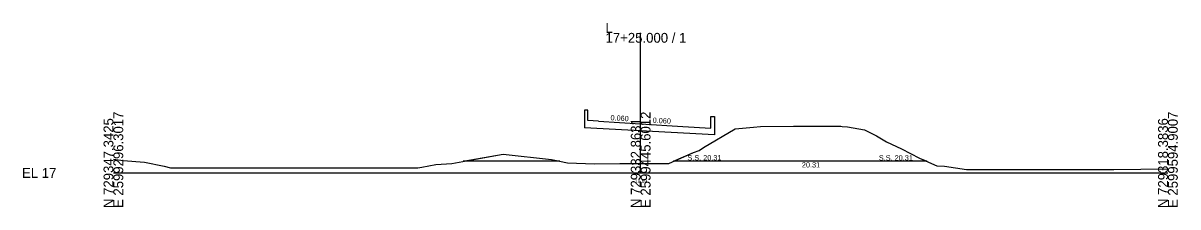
# Model space of a CAD drawing. Extents: x -26 to 3303, y -10 to 9555.
# Drawn here: x 974.3 to 1302.8, y 4490.3 to 4542.7 of the extents above; entities that cross this region are included whole.
import ezdxf

# ---------------------------------------------------------------- set-up
doc = ezdxf.new("R2010")
doc.units = 0
for name, color, linetype in [('Exist Cross Section Cell', 7, 'Continuous'), ('Exist XS Center Line Elevation Label', 7, 'Continuous'), ('Exist XS Ground Line', 7, 'Continuous'), ('Prop XS Bridge', 7, 'Continuous'), ('Prop XS Ditch Standard Text', 7, 'Continuous'), ('Prop XS Dump Level', 7, 'Continuous'), ('Prop XS Earthwork Shape', 7, 'Continuous'), ('Prop XS Finish Grade Earthwork', 7, 'Continuous'), ('Prop XS SE Text', 7, 'Continuous'), ('Prop XS SS Elevation Text', 7, 'Continuous')]:
    doc.layers.add(name, color=color, linetype=linetype)

msp = doc.modelspace()

# ---------------------------------------------------------------- linework, layer by layer
at = {"layer": 'Exist Cross Section Cell'}
for p, q in [((1150, 4500), (1150, 4539.91)), ((1000, 4500), (1150, 4500)), ((1150, 4500), (1300, 4500))]:
    msp.add_line(p, q, dxfattribs=at)
at = {"layer": 'Exist XS Ground Line'}
msp.add_lwpolyline([(1000, 4503.89), (1002.73, 4503.59), (1008.85, 4503.1), (1014.43, 4501.9), (1016.24, 4501.47), (1040.03, 4501.47), (1049.38, 4501.47), (1064.82, 4501.47), (1086.62, 4501.47), (1087.71, 4501.66), (1091.71, 4502.36), (1096.3, 4502.73), (1110.93, 4505.38), (1124.67, 4503.79), (1129.16, 4502.85), (1136.85, 4502.62), (1144.09, 4502.65), (1146.63, 4502.67), (1150, 4502.69), (1158.05, 4502.73), (1165.07, 4505.79), (1166.64, 4506.37), (1167.83, 4507.27), (1176.87, 4512.53), (1182.11, 4513), (1184.13, 4513.24), (1193.5, 4513.29), (1195.77, 4513.29), (1206.42, 4513.3), (1206.94, 4513.3), (1207.3, 4513.27), (1208.82, 4513.11), (1213.67, 4512.28), (1217.05, 4510.58), (1219.93, 4508.83), (1224.23, 4506.87), (1229.28, 4504.25), (1234.25, 4502.07), (1236.47, 4501.9), (1242.66, 4501), (1264.85, 4501), (1275.82, 4501), (1277.32, 4501), (1279.4, 4501), (1284.61, 4501), (1300, 4501.21)], dxfattribs=at)
at = {"layer": 'Prop XS Bridge'}
for p, q in [((1134, 4517.9), (1134, 4514.9)), ((1135, 4517.9), (1134, 4517.9)), ((1135, 4514.9), (1135, 4517.9)), ((1134, 4514.9), (1134, 4512.9)), ((1138, 4514.72), (1135, 4514.9)), ((1138, 4514.72), (1150, 4514)), ((1170, 4512.8), (1170, 4516.1)), ((1170, 4516.1), (1171, 4516.1)), ((1171, 4516.1), (1171, 4513.1)), ((1171, 4510.82), (1134, 4512.9)), ((1150, 4514), (1162, 4513.28)), ((1162, 4513.28), (1170, 4512.8)), ((1171, 4513.1), (1171, 4510.82))]:
    msp.add_line(p, q, dxfattribs=at)
at = {"layer": 'Prop XS Dump Level'}
for p, q in [((1138, 4514.72), (1150, 4514)), ((1150, 4514), (1162, 4513.28))]:
    msp.add_line(p, q, dxfattribs=at)
at = {"layer": 'Prop XS Earthwork Shape'}
for points in [[(1229.28, 4504.25), (1231.42, 4503.31), (1159.38, 4503.31), (1165.07, 4505.79), (1166.64, 4506.37), (1167.83, 4507.27), (1176.87, 4512.53), (1182.11, 4513), (1184.13, 4513.24), (1193.5, 4513.29), (1195.77, 4513.29), (1206.42, 4513.3), (1206.94, 4513.3), (1207.3, 4513.27), (1208.82, 4513.11), (1213.67, 4512.28), (1217.05, 4510.58), (1219.93, 4508.83), (1224.23, 4506.87)], [(1159.38, 4503.31), (1165.07, 4505.79), (1166.64, 4506.37), (1167.83, 4507.27), (1176.87, 4512.53), (1182.11, 4513), (1184.13, 4513.24), (1193.5, 4513.29), (1195.77, 4513.29), (1206.42, 4513.3), (1206.94, 4513.3), (1207.3, 4513.27), (1208.82, 4513.11), (1213.67, 4512.28), (1217.05, 4510.58), (1219.93, 4508.83), (1224.23, 4506.87), (1229.28, 4504.25), (1231.42, 4503.31)], [(1126.96, 4503.31), (1099.51, 4503.31), (1110.93, 4505.38), (1124.67, 4503.79)], [(1099.51, 4503.31), (1110.93, 4505.38), (1124.67, 4503.79), (1126.96, 4503.31)]]:
    msp.add_lwpolyline(points, close=True, dxfattribs=at)
at = {"layer": 'Prop XS Finish Grade Earthwork'}
for p, q in [((1126.96, 4503.31), (1099.51, 4503.31)), ((1231.42, 4503.31), (1159.38, 4503.31))]:
    msp.add_line(p, q, dxfattribs=at)

# ---------------------------------------------------------------- texts
at = {"layer": 'Exist Cross Section Cell'}
for s, p in [('L', (1140, 4539.91)), ('17+25.000 / 1', (1140, 4537.11)), ('EL 17', (974, 4498.6))]:
    msp.add_text(s, height=2.8, dxfattribs=at).set_placement(p)
for s, p in [('N 729347.3425', (1000, 4490)), ('E 2599296.3017', (1002.8, 4490)), ('N 729332.8631', (1150, 4490)), ('E 2599445.6012', (1152.8, 4490)), ('N 729318.3836', (1300, 4490)), ('E 2599594.9007', (1302.8, 4490))]:
    msp.add_text(s, height=2.8, rotation=90, dxfattribs=at).set_placement(p)
at = {"layer": 'Exist XS Center Line Elevation Label'}
msp.add_text('19.69', height=1, dxfattribs=at).set_placement((1148.38, 4497.19))
at = {"layer": 'Prop XS Ditch Standard Text'}
msp.add_text('20.31', height=1.5, dxfattribs=at).set_placement((1195.87, 4501.56))
at = {"layer": 'Prop XS SE Text'}
for p in [(1141.38, 4515.02), (1153.38, 4514.3)]:
    msp.add_text('0.060', height=1.5, rotation=356.5664, dxfattribs=at).set_placement(p)
at = {"layer": 'Prop XS SS Elevation Text'}
for p in [(1163.3, 4503.58), (1217.77, 4503.55)]:
    msp.add_text('S.S. 20.31', height=1.5, dxfattribs=at).set_placement(p)

doc.saveas('drawing.dxf')
